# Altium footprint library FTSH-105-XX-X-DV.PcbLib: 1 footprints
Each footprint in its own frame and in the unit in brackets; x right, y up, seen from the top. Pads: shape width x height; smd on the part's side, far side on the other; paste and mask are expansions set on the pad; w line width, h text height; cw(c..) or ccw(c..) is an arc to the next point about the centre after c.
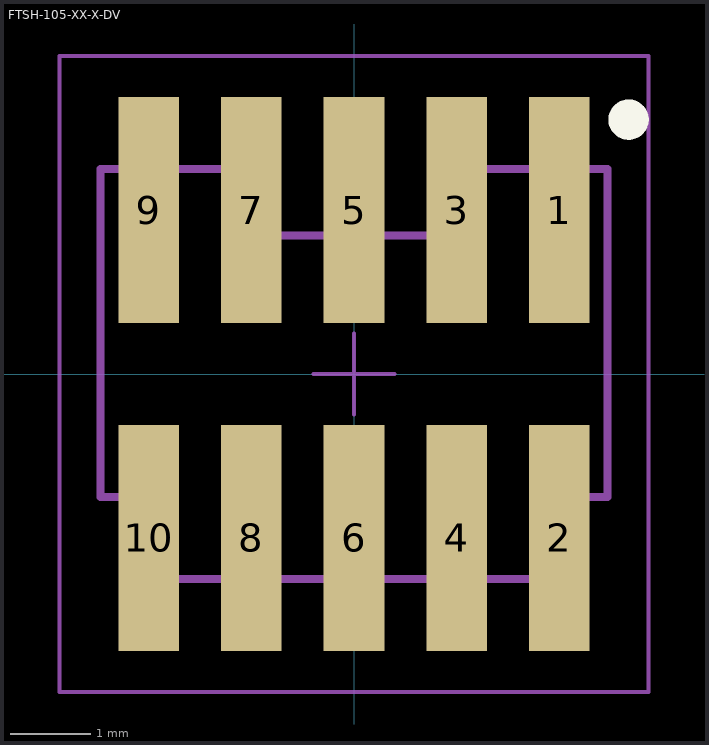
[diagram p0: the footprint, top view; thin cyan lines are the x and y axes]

## FTSH-105-XX-X-DV [mm] "1.27mm pitch, 10 pin, terminal strip; vertical, SMT"
height 5.97
pads (10):
  rect 0.75x2.8 smd mask+0: 1(2.54,2.03) 2(2.54,-2.03) 3(1.27,2.03) 4(1.27,-2.03) 5(0,2.03) 6(0,-2.03) 7(-1.27,2.03) 8(-1.27,-2.03) 9(-2.54,2.03) 10(-2.54,-2.03)
Top Overlay:
  circle w0.25: c3.4,3.15 r0.125
Mechanical 12:
  lines w0.001: -3.137,-1.524 -2.54,-1.524 -2.54,-2.54 2.54,-2.54 2.54,-1.524 3.137,-1.524 3.137,2.54 1.079,2.54 1.079,1.714 -1.079,1.714 -1.079,2.54 -3.137,2.54 -3.137,-1.524
Mechanical 13:
  lines w0.1: -3.137,-1.524 -2.54,-1.524 -2.54,-2.54 2.54,-2.54 2.54,-1.524 3.137,-1.524 3.137,2.54 1.079,2.54 1.079,1.714 -1.079,1.714 -1.079,2.54 -3.137,2.54 -3.137,-1.524
  text ".Designator" at 0.254,0.254 h1.52
Mechanical 15:
  lines w0.05: -0.5,0 0.5,0 ; 0,-0.5 0,0.5 ; -3.645,-3.937 -3.645,3.937 3.645,3.937 3.645,-3.937 -3.645,-3.937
